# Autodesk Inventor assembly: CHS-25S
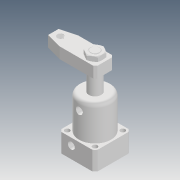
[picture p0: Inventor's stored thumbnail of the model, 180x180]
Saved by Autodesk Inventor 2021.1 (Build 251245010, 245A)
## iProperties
Created: 2019-04
Part Number: CHS-25S
Description: STEP AP203
Document SubType Name: Assembly
Designer: user
Title: chs-25s_asm.STEP
Revision Number: ÈÎºÎ
Sending System: SolidWorks 2017
Preprocessor: SwSTEP 2.0
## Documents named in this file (5)
- D:\Vault_2016\Projekty\Clamptek\Hydraulic\CHS\CHS-25\Inventor\CHS-25S\CHS-25S.iam
- D:\Vault_2016\Projekty\Clamptek\Hydraulic\CHS\CHS-25\Inventor\CHS-25S\CHS-25-03.ipt
- D:\Vault_2016\Projekty\Clamptek\Hydraulic\CHS\CHS-25\Inventor\CHS-25S\CHS-25S-02_1.ipt
- D:\Vault_2016\Projekty\Clamptek\Hydraulic\CHS\CHS-25\Inventor\CHS-25S\CHS-25-01.ipt
- D:\Vault_2016\Projekty\Clamptek\Hydraulic\CHS\CHS-25\Inventor\CHS-25S\M14.ipt
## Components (4 placed, 4 different names)
1. CHS-25-03_1
2. CHS-25S-02_1_2
3. CHS-25-01_3
4. M14_4
